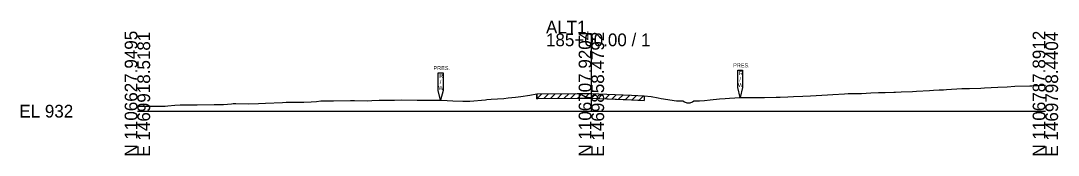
# Model space of a CAD drawing. Extents: x -26 to 2203, y -10 to 19568.
# Drawn here: x 1974.3 to 2202.8, y 6990.3 to 7019.9 of the extents above; entities that cross this region are included whole.
import ezdxf

# ---------------------------------------------------------------- set-up
doc = ezdxf.new("R2010")
doc.units = 0
for name, color, linetype in [('RD_GPK_XS_Cell', 7, 'Continuous'), ('RD_XS_ExGround', 7, 'Continuous'), ('RD_XS_ExPaveRet', 7, 'Continuous'), ('RD_XS_ExRW', 7, 'Continuous')]:
    doc.layers.add(name, color=color, linetype=linetype)

msp = doc.modelspace()

# ---------------------------------------------------------------- linework, layer by layer
at = {"layer": 'RD_GPK_XS_Cell'}
for p, q in [((2100, 7000), (2100, 7017.09)), ((2000, 7000), (2100, 7000)), ((2100, 7000), (2200, 7000))]:
    msp.add_line(p, q, dxfattribs=at)
at = {"layer": 'RD_XS_ExGround'}
msp.add_lwpolyline([(2000, 7001.12), (2001.94, 7001.09), (2002.67, 7001.09), (2005.69, 7001.12), (2006.12, 7001.11), (2006.69, 7001.17), (2008.26, 7001.35), (2009.44, 7001.38), (2011.69, 7001.4), (2013.19, 7001.43), (2016.94, 7001.45), (2018.98, 7001.5), (2020.7, 7001.65), (2021.12, 7001.69), (2021.68, 7001.68), (2024.45, 7001.65), (2026.68, 7001.7), (2028.2, 7001.74), (2031.95, 7001.94), (2032.77, 7001.95), (2035.7, 7001.96), (2036.67, 7001.95), (2038.25, 7002.04), (2039.45, 7002.14), (2040.4, 7002.24), (2041.67, 7002.26), (2043.2, 7002.3), (2046.96, 7002.34), (2047.82, 7002.32), (2050.71, 7002.29), (2051.66, 7002.32), (2053.26, 7002.44), (2054.46, 7002.45), (2056.66, 7002.44), (2058.21, 7002.48), (2061.66, 7002.43), (2061.96, 7002.42), (2062.88, 7002.42), (2065.71, 7002.4), (2066.12, 7002.41), (2066.65, 7002.4), (2068.26, 7002.36), (2069.46, 7002.27), (2071.65, 7002.19), (2072.54, 7002.19), (2073.21, 7002.21), (2076.65, 7002.53), (2076.97, 7002.56), (2077.93, 7002.63), (2080.72, 7002.81), (2081.64, 7002.9), (2083.26, 7003.05), (2084.46, 7003.25), (2086.42, 7003.52), (2088.01, 7003.78), (2096.85, 7003.87), (2099.83, 7003.87), (2108.87, 7003.49), (2111.6, 7003.36), (2113.18, 7003.2), (2114.68, 7002.91), (2115.4, 7002.8), (2118.73, 7002.3), (2119.66, 7002.25), (2120.14, 7002.25), (2120.5, 7002.06), (2121.05, 7001.85), (2121.75, 7001.85), (2122.24, 7002.04), (2122.59, 7002.25), (2123.04, 7002.26), (2123.83, 7002.3), (2124.95, 7002.38), (2126.2, 7002.48), (2128.25, 7002.73), (2129.49, 7002.77), (2130.4, 7002.86), (2131.61, 7002.93), (2132.54, 7003), (2133.24, 7003.02), (2136.61, 7003.03), (2136.99, 7003.03), (2138.13, 7003.04), (2140.74, 7003.08), (2141.11, 7003.08), (2141.61, 7003.1), (2143.25, 7003.19), (2144.49, 7003.24), (2146.6, 7003.28), (2148.24, 7003.34), (2151.99, 7003.6), (2153.18, 7003.68), (2155.74, 7003.82), (2156.6, 7003.87), (2159.5, 7003.91), (2161.59, 7004.01), (2163.25, 7004.08), (2164.68, 7004.09), (2166.59, 7004.18), (2167, 7004.19), (2168.23, 7004.24), (2170.75, 7004.35), (2171.59, 7004.4), (2174.5, 7004.56), (2175.39, 7004.6), (2176.58, 7004.66), (2177.54, 7004.73), (2178.25, 7004.76), (2181.58, 7004.96), (2182, 7004.98), (2183.29, 7005.01), (2185.76, 7005.08), (2186.58, 7005.12), (2189.51, 7005.3), (2191.57, 7005.37), (2193.26, 7005.48), (2196.57, 7005.58), (2197.01, 7005.59), (2198.34, 7005.63), (2200, 7005.7)], dxfattribs=at)
at = {"layer": 'RD_XS_ExPaveRet'}
for p, q in [((2088.01, 7002.74), (2089.06, 7003.79)), ((2088.01, 7003.78), (2088.01, 7002.78)), ((2088.01, 7002.74), (2088.01, 7003.74)), ((2088.01, 7002.78), (2096.85, 7002.87)), ((2088.01, 7002.77), (2088.24, 7002.8)), ((2088.01, 7002.74), (2088.24, 7002.78)), ((2088.24, 7002.8), (2096.91, 7002.89)), ((2088.24, 7002.78), (2097.14, 7002.86)), ((2089.51, 7002.79), (2090.52, 7003.8)), ((2091.01, 7002.81), (2092.02, 7003.81)), ((2092.51, 7002.82), (2093.52, 7003.83)), ((2094.01, 7002.83), (2095.02, 7003.84)), ((2095.51, 7002.85), (2096.52, 7003.86)), ((2096.85, 7002.87), (2099.83, 7002.87)), ((2096.91, 7002.89), (2100.05, 7002.88)), ((2097.01, 7002.89), (2097.99, 7003.86)), ((2097.14, 7002.86), (2100.05, 7002.86)), ((2098.51, 7002.86), (2099.51, 7003.86)), ((2099.83, 7002.87), (2108.87, 7002.49)), ((2100.01, 7002.86), (2100.97, 7003.82)), ((2100.05, 7002.88), (2108.96, 7002.51)), ((2100.05, 7002.86), (2109.19, 7002.48)), ((2101.51, 7002.8), (2102.47, 7003.76)), ((2103.01, 7002.74), (2103.97, 7003.69)), ((2104.51, 7002.67), (2105.47, 7003.63)), ((2106.01, 7002.61), (2106.97, 7003.57)), ((2107.51, 7002.55), (2108.47, 7003.51)), ((2108.87, 7002.49), (2111.6, 7002.36)), ((2108.96, 7002.51), (2111.6, 7002.38)), ((2109.01, 7002.51), (2109.94, 7003.44)), ((2109.19, 7002.48), (2111.6, 7002.36)), ((2110.51, 7002.41), (2111.46, 7003.37)), ((2111.6, 7003.38), (2111.6, 7002.38)), ((2111.6, 7003.36), (2111.6, 7002.36))]:
    msp.add_line(p, q, dxfattribs=at)
at = {"layer": 'RD_XS_ExRW'}
for points in [[(2066.23, 7008.41), (2067.32, 7008.41), (2067.32, 7004.58), (2066.77, 7002.4), (2066.23, 7004.58)], [(2132.23, 7009.02), (2133.32, 7009.02), (2133.32, 7005.19), (2132.77, 7003), (2132.23, 7005.19)]]:
    msp.add_lwpolyline(points, close=True, dxfattribs=at)

# ---------------------------------------------------------------- texts
at = {"layer": 'RD_GPK_XS_Cell'}
for s, p in [('ALT1', (2090, 7017.09)), ('185+00.00 / 1', (2090, 7014.29)), ('EL 932', (1974, 6998.6))]:
    msp.add_text(s, height=2.8, dxfattribs=at).set_placement(p)
for s, p in [('N 1106627.9495', (2000, 6990)), ('E 1469918.5181', (2002.8, 6990)), ('N 1106707.9204', (2100, 6990)), ('E 1469858.4792', (2102.8, 6990)), ('N 1106787.8912', (2200, 6990)), ('E 1469798.4404', (2202.8, 6990))]:
    msp.add_text(s, height=2.8, rotation=90, dxfattribs=at).set_placement(p)
at = {"layer": 'RD_XS_ExRW'}
for s, p in [('PRES.', (2065.23, 7009.04)), ('PRES.', (2131.23, 7009.64)), ('R', (2066.49, 7007.32)), ('/', (2066.61, 7006.01)), ('R', (2132.49, 7007.93)), ('/', (2132.61, 7006.61)), ('W', (2066.3, 7004.69)), ('W', (2132.3, 7005.3))]:
    msp.add_text(s, height=0.875, dxfattribs=at).set_placement(p)

doc.saveas('drawing.dxf')
